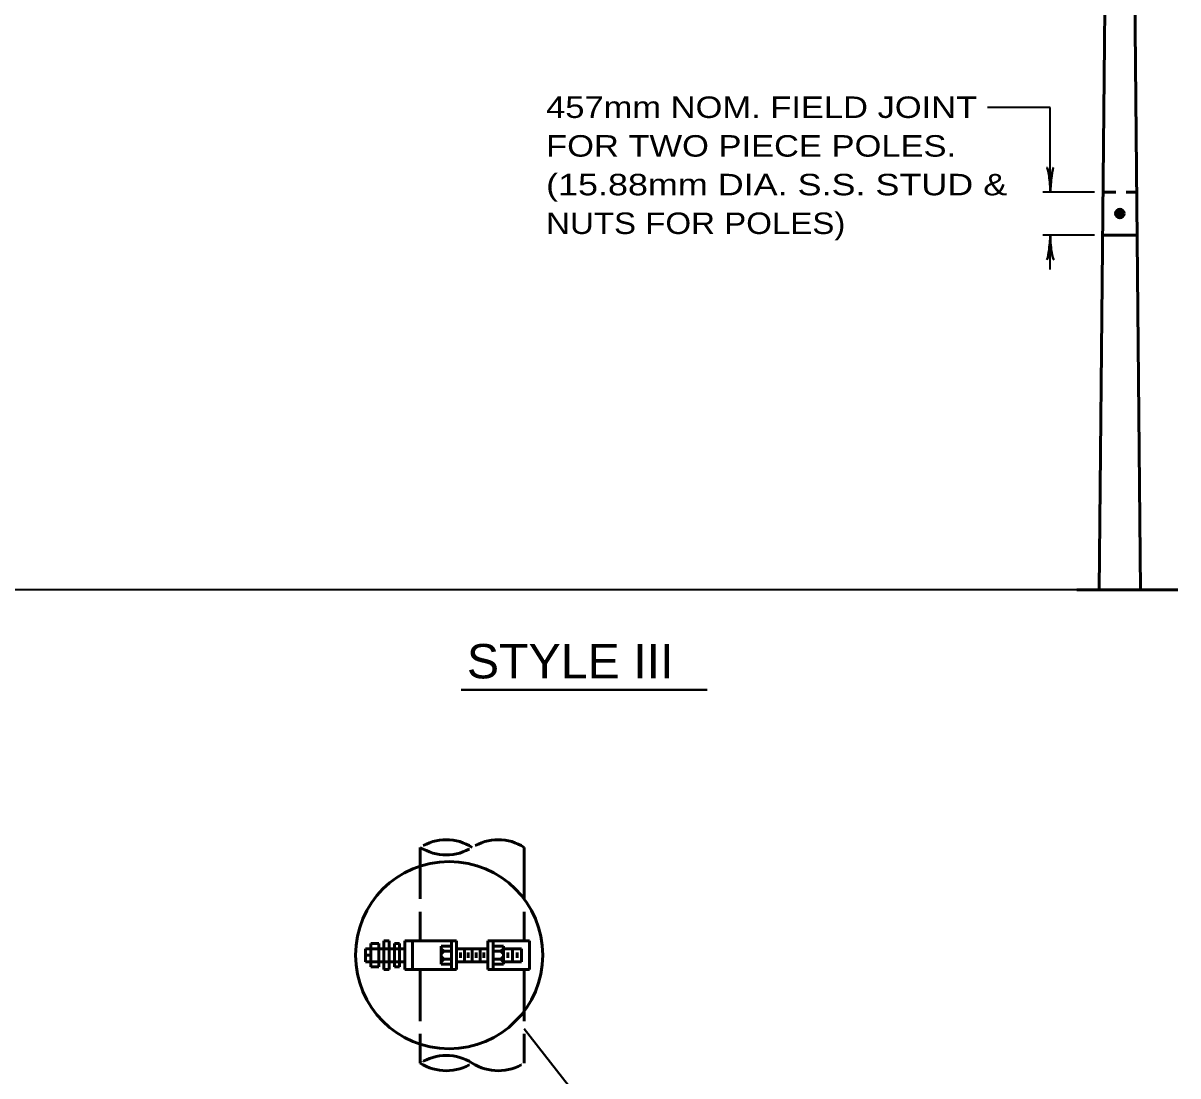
# Model space of a CAD drawing. Extents: x -23 to 690, y -228 to 443.
# Drawn here: x 61.8 to 196.1, y 192.8 to 315.3 of the extents above; entities that cross this region are included whole.
import ezdxf

# ---------------------------------------------------------------- set-up
doc = ezdxf.new("R2010")
doc.units = 0
doc.linetypes.add('LONG_DASHED', pattern=[7.5, 6, -1.5])
doc.linetypes.add('SHORT_DASHED', pattern=[2.7, 1.5, -1.2])
doc.layers.add('1', color=7, linetype='Continuous', lineweight=35)

msp = doc.modelspace()

# ---------------------------------------------------------------- hatches: boundary and pattern name
at = {"layer": '1'}
msp.add_hatch(color=256, dxfattribs=at).paths.add_polyline_path([(189.888, 293.165, 1), (188.888, 293.165, 1)])

# ---------------------------------------------------------------- linework, layer by layer
at = {"layer": '1', "lineweight": 53}
for p, q in [((190.893, 344.411), (191.784, 249.412)), ((187.389, 290.661), (191.397, 290.661)), ((184.393, 249.411), (196.143, 249.411)), ((102.247, 208.25), (102.247, 205.53)), ((102.247, 208.25), (103.167, 208.25)), ((103.167, 208.25), (103.167, 205.53)), ((103.767, 208.55), (103.767, 205.231)), ((103.767, 208.55), (104.367, 208.55)), ((104.367, 208.55), (104.367, 205.231)), ((104.987, 208.25), (104.987, 205.53)), ((104.987, 208.25), (105.587, 208.25)), ((105.587, 208.25), (105.587, 205.53)), ((106.187, 208.55), (106.187, 205.231)), ((106.187, 208.55), (112.227, 208.55)), ((107.087, 208.55), (107.087, 205.231)), ((111.627, 208.55), (111.627, 205.231)), ((112.227, 208.55), (112.227, 205.231)), ((115.867, 208.55), (115.867, 205.231)), ((115.867, 208.55), (120.707, 208.55)), ((116.467, 208.55), (116.467, 205.231)), ((120.707, 208.55), (120.707, 205.231)), ((101.647, 207.65), (101.647, 206.13)), ((101.647, 207.65), (106.187, 207.65)), ((101.947, 207.03), (101.947, 206.731)), ((110.427, 207.951), (111.627, 207.951)), ((110.427, 207.951), (110.427, 205.831)), ((110.727, 207.35), (111.627, 207.35)), ((112.687, 207.19), (112.687, 206.59)), ((113.147, 207.65), (113.147, 206.13)), ((113.587, 207.19), (113.587, 206.59)), ((114.047, 207.65), (114.047, 206.13)), ((114.507, 207.19), (114.507, 206.59)), ((114.967, 207.65), (114.967, 206.13)), ((115.407, 207.19), (115.407, 206.59)), ((117.687, 207.951), (116.487, 207.951)), ((117.387, 207.35), (116.487, 207.35)), ((117.687, 207.951), (117.687, 205.831)), ((118.207, 207.19), (118.207, 206.59)), ((118.747, 207.65), (118.747, 206.13)), ((119.267, 207.19), (119.267, 206.59)), ((119.787, 207.65), (119.787, 206.13)), ((101.647, 206.13), (106.187, 206.13)), ((110.427, 205.831), (111.627, 205.831)), ((110.727, 206.43), (111.627, 206.43)), ((117.387, 206.43), (116.487, 206.43)), ((117.687, 205.831), (116.487, 205.831)), ((117.687, 206.731), (117.387, 206.43)), ((117.387, 206.43), (117.687, 206.13)), ((102.247, 205.53), (103.167, 205.53)), ((103.767, 205.231), (104.367, 205.231)), ((105.587, 205.53), (104.987, 205.53)), ((112.227, 205.231), (106.187, 205.231)), ((115.867, 205.231), (120.707, 205.231))]:
    msp.add_line(p, q, dxfattribs=at)
at = {"layer": '1'}
for p, q in [((181.298, 305.522), (174.004, 305.522)), ((181.298, 295.661), (181.298, 305.522)), ((186.436, 295.661), (180.436, 295.661)), ((186.436, 290.661), (180.436, 290.661)), ((181.298, 286.661), (181.298, 290.661)), ((184.393, 249.411), (54.189, 249.411))]:
    msp.add_line(p, q, dxfattribs=at)
at = {"layer": '1', "linetype": 'SHORT_DASHED', "lineweight": 53}
msp.add_line((187.436, 295.661), (191.35, 295.661), dxfattribs=at)
at = {"layer": '1', "lineweight": 40}
for p, q in [((112.77, 237.748), (141.364, 237.748)), ((120.107, 198.311), (130.625, 184.906))]:
    msp.add_line(p, q, dxfattribs=at)
at = {"layer": '1', "linetype": 'LONG_DASHED', "lineweight": 53}
for p, q in [((108.007, 219.43), (108.007, 208.55)), ((120.107, 219.43), (120.107, 208.55)), ((108.007, 205.231), (108.007, 194.331)), ((120.107, 205.231), (120.107, 194.331))]:
    msp.add_line(p, q, dxfattribs=at)
at = {"layer": '1', "lineweight": 53}
for points in [[(187.893, 344.411), (187.86, 340.911), (187.823, 336.911), (187.002, 249.412)], [(110.427, 207.65), (110.727, 207.35), (110.427, 207.03)], [(112.227, 207.65), (113.147, 207.65), (114.047, 207.65), (114.967, 207.65), (115.867, 207.65)], [(117.687, 207.65), (117.387, 207.35), (117.687, 207.03)], [(117.687, 207.65), (118.747, 207.65), (119.787, 207.65)], [(110.427, 206.731), (110.727, 206.43), (110.427, 206.13)], [(112.227, 206.13), (114.047, 206.13), (115.867, 206.13)], [(117.687, 206.13), (118.747, 206.13), (119.787, 206.13)]]:
    msp.add_lwpolyline(points, dxfattribs=at)
for centre, radius in [((189.388, 293.165), 0.5), ((111.362, 206.894), 10.886)]:
    msp.add_circle(centre, radius, dxfattribs=at)
at = {"layer": '1', "linetype": 'LONG_DASHED', "lineweight": 53}
for centre, start, end in [((111.027, 214.705), 57.42639, 122.57361), ((111.027, 224.172), 237.42639, 302.57361), ((117.075, 214.705), 57.42639, 122.57361), ((111.027, 189.606), 57.42639, 122.57361), ((111.027, 199.073), 237.42639, 302.57361), ((117.075, 199.073), 237.42639, 302.57361)]:
    msp.add_arc(centre, 5.617, start, end, dxfattribs=at)
at = {"layer": '1', "lineweight": 40}
for centre, major_axis, ratio, start_param, end_param in [((181.021, 296.752), (0.156, -1.786), 0.122415, 0.8963533, 3.1415927), ((181.021, 296.752), (0.156, -1.786), 0.122415, 0.8963533, 3.1415927), ((181.509, 296.782), (-0.176, -1.756), 0.07063, 3.1407148, 5.41811), ((181.509, 296.782), (-0.176, -1.756), 0.07063, 3.1407148, 5.41811), ((181.086, 289.541), (0.176, 1.756), 0.07063, 3.1407148, 5.41811), ((181.086, 289.541), (0.176, 1.756), 0.07063, 3.1407148, 5.41811), ((181.574, 289.57), (-0.156, 1.786), 0.122415, 0.8963533, 3.1415927), ((181.574, 289.57), (-0.156, 1.786), 0.122415, 0.8963533, 3.1415927)]:
    msp.add_ellipse(centre, major_axis=major_axis, ratio=ratio, start_param=start_param, end_param=end_param, dxfattribs=at)

# ---------------------------------------------------------------- texts
at = {"layer": '1'}
for s, height, width, p in [('457mm NOM. FIELD JOINT', 2.5, 1.2, (122.639, 304.291)), ('FOR TWO PIECE POLES.', 2.5, 1.2, (122.639, 299.791)), ('(15.88mm DIA. S.S. STUD &', 2.5, 1.25, (122.639, 295.291)), ('NUTS FOR POLES)', 2.5, 1.15, (122.639, 290.791)), ('STYLE III', 4, 1.05, (113.424, 239.093))]:
    msp.add_text(s, height=height, dxfattribs=dict(at, width=width)).set_placement(p)

doc.saveas('drawing.dxf')
